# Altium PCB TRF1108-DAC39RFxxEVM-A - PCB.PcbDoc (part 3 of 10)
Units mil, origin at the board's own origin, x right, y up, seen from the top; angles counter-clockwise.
Board outline 4951.22 x 2726.56 mil, 16 copper layers (Top Layer, L2 GND1, L3 PWR1, L4 GND2, L5 PWR2, L6 GND3, L7 Ctrl Signal 1, L8 GND4, L9 GND5, L10 Ctrl Signal 2, L11 GND6, L12 PWR3, L13 GND7, L14 PWR4, L15 GND8, Bottom Layer), stack 80.2 mil thick; 705 components, 433 nets, 3633 pads, 1678 vias.
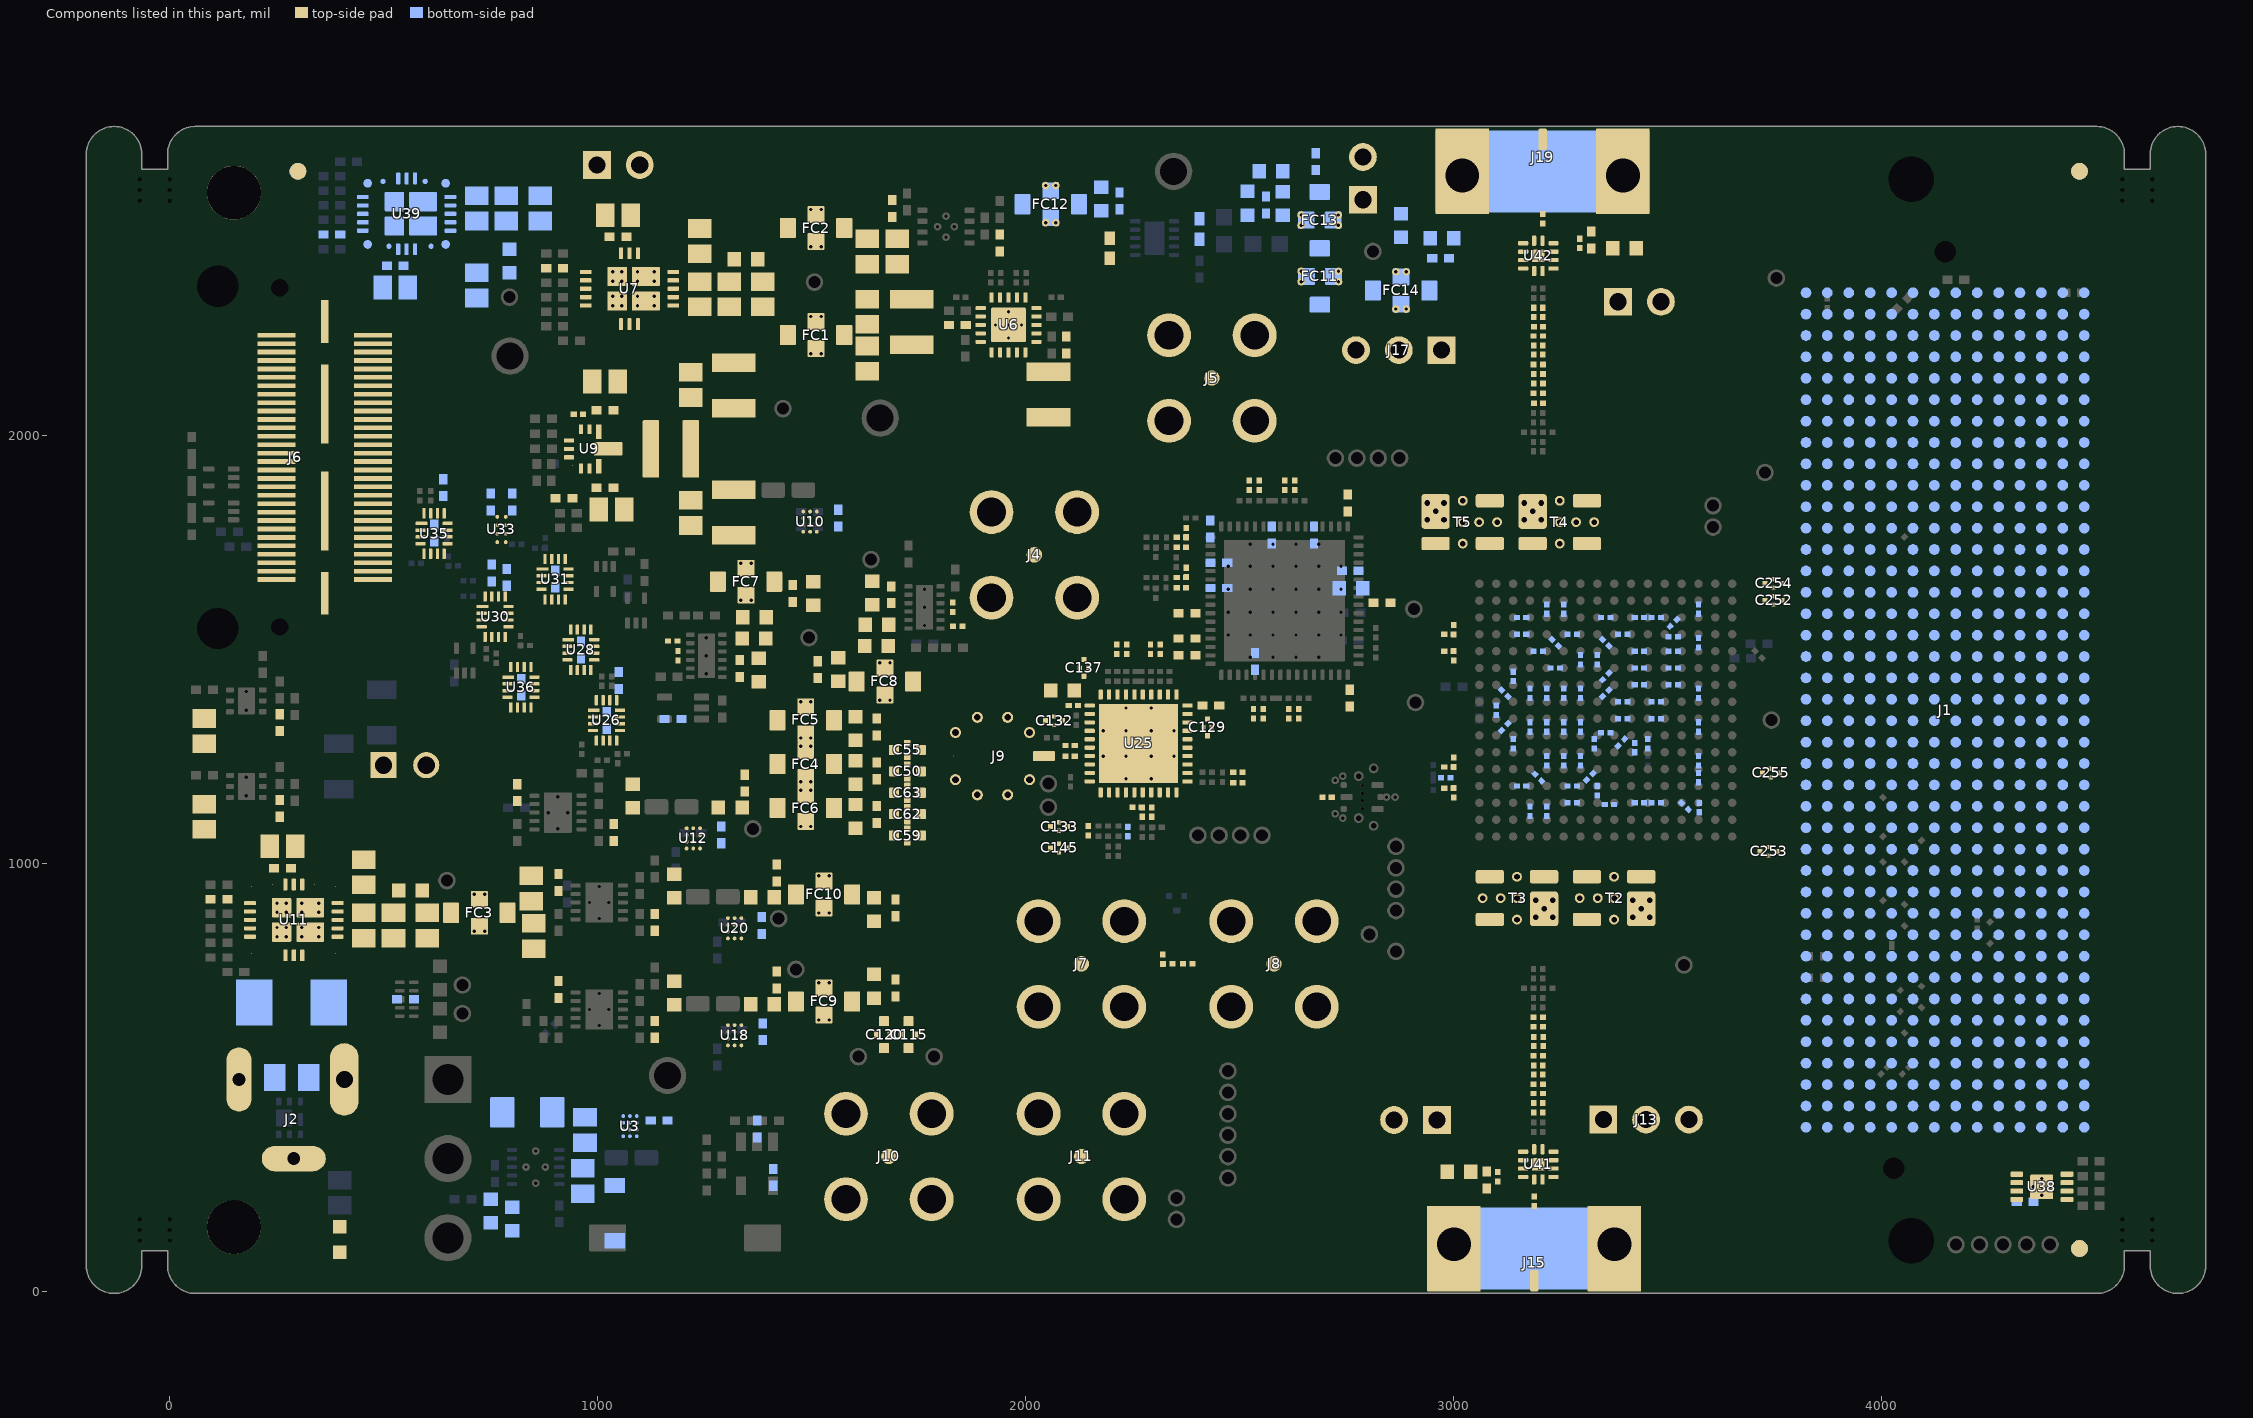
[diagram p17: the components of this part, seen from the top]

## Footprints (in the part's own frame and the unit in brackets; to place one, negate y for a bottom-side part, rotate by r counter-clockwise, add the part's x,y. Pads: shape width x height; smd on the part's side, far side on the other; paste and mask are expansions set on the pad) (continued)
RDU0028A [mm]
  round 0.025 smd mask+0.05: 1(-1.987,2.487) 2(-2.1,1.25) 6(-2.1,-1.25) 7(-1.987,-2.488) 13(1.987,-2.488) 14(2.1,-1.25) 18(2.1,1.25) 19(1.988,2.488)
  rrect40% 0.7x0.25 smd paste+0 mask+0.05: 3(-2.1,0.5) 4(-2.1,0) 5(-2.1,-0.5) 15(2.1,-0.5) 16(2.1,0) 17(2.1,0.5)
  rrect40% 0.25x0.7 smd paste+0 mask+0.05: 8(-1,-2.6) 9(-0.5,-2.6) 10(0,-2.6) 11(0.5,-2.6) 12(1,-2.6) 20(1,2.6) 21(0.5,2.6) 22(0,2.6) 23(-0.5,2.6) 24(-1,2.6)
  round 0.454 hole 0.2 mask+0.102: 25(-1,1) 25(-1,0.45) 25(-0.45,1) 25(-0.45,0.45) 26(-1,-0.475) 26(-1,-1.475) 26(-0.45,-0.475) 26(-0.45,-1.475) 27(0.45,-0.475) 27(0.45,-1.475) 27(1,-0.475) 27(1,-1.475) 28(0.45,1) 28(0.45,0.45) 28(1,1) 28(1,0.45)
  rrect9% 1.15x1.15 smd paste-1000 mask+0.05: 25(-0.725,0.725) 28(0.725,0.725)
  rrect9% 1.15x1.65 smd paste-1000 mask+0.05: 26(-0.725,-0.975) 27(0.725,-0.975)
  Top Layer region: -1.575,2.95 -1.55,2.943 -1.532,2.925 -1.525,2.9 -1.525,2.9 -1.525,2.075 -1.529,2.056 -1.54,2.04 -1.556,2.029 -1.575,2.025 -1.575,2.025 -2.4,2.025 -2.423,2.033 -2.439,2.051 -2.445,2.075 -2.445,2.075 -2.45,2.225 -2.443,2.25 -2.425,2.268 -2.4,2.275 -2.4,2.275 -2.225,2.275 -2.187,2.283 -2.154,2.304 -2.133,2.337 -2.125,2.375 -2.125,2.375 -2.125,2.575 -2.118,2.6 -2.1,2.618 -2.075,2.625 -2.075,2.625 -1.875,2.625 -1.837,2.633 -1.804,2.654 -1.783,2.687 -1.775,2.725 -1.775,2.725 -1.775,2.9 -1.768,2.925 -1.75,2.943 -1.725,2.95 -1.725,2.95
  Top Layer region: -1.575,-2.95 -1.55,-2.943 -1.532,-2.925 -1.525,-2.9 -1.525,-2.9 -1.525,-2.075 -1.529,-2.056 -1.54,-2.04 -1.556,-2.029 -1.575,-2.025 -1.575,-2.025 -2.4,-2.025 -2.423,-2.033 -2.439,-2.051 -2.445,-2.075 -2.445,-2.075 -2.45,-2.225 -2.443,-2.25 -2.425,-2.268 -2.4,-2.275 -2.4,-2.275 -2.225,-2.275 -2.187,-2.283 -2.154,-2.304 -2.133,-2.337 -2.125,-2.375 -2.125,-2.375 -2.125,-2.575 -2.118,-2.6 -2.1,-2.618 -2.075,-2.625 -2.075,-2.625 -1.875,-2.625 -1.837,-2.633 -1.804,-2.654 -1.783,-2.687 -1.775,-2.725 -1.775,-2.725 -1.775,-2.9 -1.768,-2.925 -1.75,-2.943 -1.725,-2.95 -1.725,-2.95
  Top Layer region: -2.4,-0.875 -1.8,-0.875 -1.775,-0.882 -1.757,-0.9 -1.75,-0.925 -1.75,-0.925 -1.75,-1.575 -1.754,-1.594 -1.765,-1.61 -1.781,-1.621 -1.8,-1.625 -1.8,-1.625 -2.4,-1.625 -2.419,-1.621 -2.435,-1.61 -2.446,-1.594 -2.45,-1.575 -2.45,-1.575 -2.45,-1.425 -2.443,-1.4 -2.425,-1.382 -2.4,-1.375 -2.4,-1.375 -2.225,-1.375 -2.187,-1.367 -2.154,-1.346 -2.133,-1.313 -2.125,-1.275 -2.125,-1.275 -2.125,-1.225 -2.138,-1.175 -2.175,-1.138 -2.225,-1.125 -2.225,-1.125 -2.4,-1.125 -2.419,-1.121 -2.435,-1.11 -2.446,-1.094 -2.45,-1.075 -2.45,-1.075 -2.45,-0.925 -2.443,-0.9 -2.425,-0.882 -2.4,-0.875
  Top Layer region: -2.4,1.625 -1.8,1.625 -1.781,1.621 -1.765,1.61 -1.754,1.594 -1.75,1.575 -1.75,1.575 -1.75,0.925 -1.754,0.906 -1.765,0.89 -1.781,0.879 -1.8,0.875 -1.8,0.875 -2.4,0.875 -2.419,0.879 -2.435,0.89 -2.446,0.906 -2.45,0.925 -2.45,0.925 -2.45,1.075 -2.443,1.1 -2.425,1.118 -2.4,1.125 -2.4,1.125 -2.225,1.125 -2.187,1.133 -2.154,1.154 -2.133,1.187 -2.125,1.225 -2.125,1.225 -2.125,1.275 -2.138,1.325 -2.175,1.362 -2.225,1.375 -2.225,1.375 -2.4,1.375 -2.419,1.379 -2.435,1.39 -2.446,1.406 -2.45,1.425 -2.45,1.425 -2.45,1.575 -2.443,1.6 -2.425,1.618 -2.4,1.625
  Top Layer region: 1.575,2.95 1.55,2.943 1.532,2.925 1.525,2.9 1.525,2.9 1.525,2.075 1.529,2.056 1.54,2.04 1.556,2.029 1.575,2.025 1.575,2.025 2.4,2.025 2.423,2.033 2.439,2.051 2.445,2.075 2.445,2.075 2.45,2.225 2.443,2.25 2.425,2.268 2.4,2.275 2.4,2.275 2.225,2.275 2.187,2.283 2.154,2.304 2.133,2.337 2.125,2.375 2.125,2.375 2.125,2.575 2.118,2.6 2.1,2.618 2.075,2.625 2.075,2.625 1.875,2.625 1.837,2.633 1.804,2.654 1.783,2.687 1.775,2.725 1.775,2.725 1.775,2.9 1.768,2.925 1.75,2.943 1.725,2.95 1.725,2.95
  Top Layer region: 2.4,0.875 1.8,0.875 1.775,0.882 1.757,0.9 1.75,0.925 1.75,0.925 1.75,1.575 1.754,1.594 1.765,1.61 1.781,1.621 1.8,1.625 1.8,1.625 2.4,1.625 2.419,1.621 2.435,1.61 2.446,1.594 2.45,1.575 2.45,1.575 2.45,1.425 2.443,1.4 2.425,1.382 2.4,1.375 2.4,1.375 2.225,1.375 2.187,1.367 2.154,1.346 2.133,1.313 2.125,1.275 2.125,1.275 2.125,1.225 2.138,1.175 2.175,1.138 2.225,1.125 2.225,1.125 2.4,1.125 2.419,1.121 2.435,1.11 2.446,1.094 2.45,1.075 2.45,1.075 2.45,0.925 2.443,0.9 2.425,0.882 2.4,0.875
  Top Layer region: 2.4,-1.625 1.8,-1.625 1.775,-1.618 1.757,-1.6 1.75,-1.575 1.75,-1.575 1.75,-0.925 1.754,-0.906 1.765,-0.89 1.781,-0.879 1.8,-0.875 1.8,-0.875 2.4,-0.875 2.419,-0.879 2.435,-0.89 2.446,-0.906 2.45,-0.925 2.45,-0.925 2.45,-1.075 2.443,-1.1 2.425,-1.118 2.4,-1.125 2.4,-1.125 2.225,-1.125 2.187,-1.133 2.154,-1.154 2.133,-1.187 2.125,-1.225 2.125,-1.225 2.125,-1.275 2.138,-1.325 2.175,-1.362 2.225,-1.375 2.225,-1.375 2.4,-1.375 2.419,-1.379 2.435,-1.39 2.446,-1.406 2.45,-1.425 2.45,-1.425 2.45,-1.575 2.443,-1.6 2.425,-1.618 2.4,-1.625
  Top Layer region: 1.575,-2.95 1.55,-2.943 1.532,-2.925 1.525,-2.9 1.525,-2.9 1.525,-2.075 1.529,-2.056 1.54,-2.04 1.556,-2.029 1.575,-2.025 1.575,-2.025 2.4,-2.025 2.423,-2.033 2.439,-2.051 2.445,-2.075 2.445,-2.075 2.45,-2.225 2.443,-2.25 2.425,-2.268 2.4,-2.275 2.4,-2.275 2.225,-2.275 2.187,-2.283 2.154,-2.304 2.133,-2.337 2.125,-2.375 2.125,-2.375 2.125,-2.575 2.118,-2.6 2.1,-2.618 2.075,-2.625 2.075,-2.625 1.875,-2.625 1.837,-2.633 1.804,-2.654 1.783,-2.687 1.775,-2.725 1.775,-2.725 1.775,-2.9 1.768,-2.925 1.75,-2.943 1.725,-2.95 1.725,-2.95
  silkscreen extent -3.2,-3.13 2.63,3.13, body extent -2.55,-3.05 2.55,3.05, height 0.25
RDU0028A-MFG [mm]
  round 0.52 smd paste+0 mask+0: 1(-1.814,2.314) 7(-1.814,-2.314) 13(1.814,-2.314) 19(1.814,2.314)
  round 0.315 smd paste+0 mask+0: 2(-1.925,1.4) 6(-1.925,-1.1) 14(1.925,-1.45) 18(1.925,1.05)
  rrect40% 0.7x0.25 smd paste+0 mask+0: 3(-2.1,0.5) 4(-2.1,0) 5(-2.1,-0.5) 15(2.1,-0.5) 16(2.1,0) 17(2.1,0.5)
  rrect40% 0.25x0.7 smd paste+0 mask+0: 8(-1,-2.6) 9(-0.5,-2.6) 10(0,-2.6) 11(0.5,-2.6) 12(1,-2.6) 20(1,2.6) 21(0.5,2.6) 22(0,2.6) 23(-0.5,2.6) 24(-1,2.6)
  rrect9% 1.15x1.15 smd paste-1000 mask+0: 25(-0.725,0.725) 28(0.725,0.725)
  rrect9% 1.15x1.65 smd paste-1000 mask+0: 26(-0.725,-0.975) 27(0.725,-0.975)
  Top Layer region: -1.575,2.95 -1.55,2.943 -1.532,2.925 -1.525,2.9 -1.525,2.9 -1.525,2.075 -1.529,2.056 -1.54,2.04 -1.556,2.029 -1.575,2.025 -1.575,2.025 -2.4,2.025 -2.423,2.033 -2.439,2.051 -2.445,2.075 -2.445,2.075 -2.45,2.225 -2.443,2.25 -2.425,2.268 -2.4,2.275 -2.4,2.275 -2.225,2.275 -2.187,2.283 -2.154,2.304 -2.133,2.337 -2.125,2.375 -2.125,2.375 -2.125,2.575 -2.118,2.6 -2.1,2.618 -2.075,2.625 -2.075,2.625 -1.875,2.625 -1.837,2.633 -1.804,2.654 -1.783,2.687 -1.775,2.725 -1.775,2.725 -1.775,2.9 -1.768,2.925 -1.75,2.943 -1.725,2.95 -1.725,2.95
  Top Layer region: -1.575,-2.95 -1.55,-2.943 -1.532,-2.925 -1.525,-2.9 -1.525,-2.9 -1.525,-2.075 -1.529,-2.056 -1.54,-2.04 -1.556,-2.029 -1.575,-2.025 -1.575,-2.025 -2.4,-2.025 -2.423,-2.033 -2.439,-2.051 -2.445,-2.075 -2.445,-2.075 -2.45,-2.225 -2.443,-2.25 -2.425,-2.268 -2.4,-2.275 -2.4,-2.275 -2.225,-2.275 -2.187,-2.283 -2.154,-2.304 -2.133,-2.337 -2.125,-2.375 -2.125,-2.375 -2.125,-2.575 -2.118,-2.6 -2.1,-2.618 -2.075,-2.625 -2.075,-2.625 -1.875,-2.625 -1.837,-2.633 -1.804,-2.654 -1.783,-2.687 -1.775,-2.725 -1.775,-2.725 -1.775,-2.9 -1.768,-2.925 -1.75,-2.943 -1.725,-2.95 -1.725,-2.95
  Top Layer region: 1.575,-2.95 1.55,-2.943 1.532,-2.925 1.525,-2.9 1.525,-2.9 1.525,-2.075 1.529,-2.056 1.54,-2.04 1.556,-2.029 1.575,-2.025 1.575,-2.025 2.4,-2.025 2.423,-2.033 2.439,-2.051 2.445,-2.075 2.445,-2.075 2.45,-2.225 2.443,-2.25 2.425,-2.268 2.4,-2.275 2.4,-2.275 2.225,-2.275 2.187,-2.283 2.154,-2.304 2.133,-2.337 2.125,-2.375 2.125,-2.375 2.125,-2.575 2.118,-2.6 2.1,-2.618 2.075,-2.625 2.075,-2.625 1.875,-2.625 1.837,-2.633 1.804,-2.654 1.783,-2.687 1.775,-2.725 1.775,-2.725 1.775,-2.9 1.768,-2.925 1.75,-2.943 1.725,-2.95 1.725,-2.95
  Top Layer region: 1.575,2.95 1.55,2.943 1.532,2.925 1.525,2.9 1.525,2.9 1.525,2.075 1.529,2.056 1.54,2.04 1.556,2.029 1.575,2.025 1.575,2.025 2.4,2.025 2.423,2.033 2.439,2.051 2.445,2.075 2.445,2.075 2.45,2.225 2.443,2.25 2.425,2.268 2.4,2.275 2.4,2.275 2.225,2.275 2.187,2.283 2.154,2.304 2.133,2.337 2.125,2.375 2.125,2.375 2.125,2.575 2.118,2.6 2.1,2.618 2.075,2.625 2.075,2.625 1.875,2.625 1.837,2.633 1.804,2.654 1.783,2.687 1.775,2.725 1.775,2.725 1.775,2.9 1.768,2.925 1.75,2.943 1.725,2.95 1.725,2.95
  Top Layer region: -2.4,1.625 -1.8,1.625 -1.781,1.621 -1.765,1.61 -1.754,1.594 -1.75,1.575 -1.75,1.575 -1.75,0.925 -1.754,0.906 -1.765,0.89 -1.781,0.879 -1.8,0.875 -1.8,0.875 -2.4,0.875 -2.419,0.879 -2.435,0.89 -2.446,0.906 -2.45,0.925 -2.45,0.925 -2.45,1.075 -2.443,1.1 -2.425,1.118 -2.4,1.125 -2.4,1.125 -2.225,1.125 -2.187,1.133 -2.154,1.154 -2.133,1.187 -2.125,1.225 -2.125,1.225 -2.125,1.275 -2.138,1.325 -2.175,1.362 -2.225,1.375 -2.225,1.375 -2.4,1.375 -2.419,1.379 -2.435,1.39 -2.446,1.406 -2.45,1.425 -2.45,1.425 -2.45,1.575 -2.443,1.6 -2.425,1.618 -2.4,1.625
  Top Layer region: -2.4,-0.875 -1.8,-0.875 -1.775,-0.882 -1.757,-0.9 -1.75,-0.925 -1.75,-0.925 -1.75,-1.575 -1.754,-1.594 -1.765,-1.61 -1.781,-1.621 -1.8,-1.625 -1.8,-1.625 -2.4,-1.625 -2.419,-1.621 -2.435,-1.61 -2.446,-1.594 -2.45,-1.575 -2.45,-1.575 -2.45,-1.425 -2.443,-1.4 -2.425,-1.382 -2.4,-1.375 -2.4,-1.375 -2.225,-1.375 -2.187,-1.367 -2.154,-1.346 -2.133,-1.313 -2.125,-1.275 -2.125,-1.275 -2.125,-1.225 -2.138,-1.175 -2.175,-1.138 -2.225,-1.125 -2.225,-1.125 -2.4,-1.125 -2.419,-1.121 -2.435,-1.11 -2.446,-1.094 -2.45,-1.075 -2.45,-1.075 -2.45,-0.925 -2.443,-0.9 -2.425,-0.882 -2.4,-0.875
  Top Layer region: 2.4,-1.625 1.8,-1.625 1.775,-1.618 1.757,-1.6 1.75,-1.575 1.75,-1.575 1.75,-0.925 1.754,-0.906 1.765,-0.89 1.781,-0.879 1.8,-0.875 1.8,-0.875 2.4,-0.875 2.419,-0.879 2.435,-0.89 2.446,-0.906 2.45,-0.925 2.45,-0.925 2.45,-1.075 2.443,-1.1 2.425,-1.118 2.4,-1.125 2.4,-1.125 2.225,-1.125 2.187,-1.133 2.154,-1.154 2.133,-1.187 2.125,-1.225 2.125,-1.225 2.125,-1.275 2.138,-1.325 2.175,-1.362 2.225,-1.375 2.225,-1.375 2.4,-1.375 2.419,-1.379 2.435,-1.39 2.446,-1.406 2.45,-1.425 2.45,-1.425 2.45,-1.575 2.443,-1.6 2.425,-1.618 2.4,-1.625
  Top Layer region: 2.4,0.875 1.8,0.875 1.775,0.882 1.757,0.9 1.75,0.925 1.75,0.925 1.75,1.575 1.754,1.594 1.765,1.61 1.781,1.621 1.8,1.625 1.8,1.625 2.4,1.625 2.419,1.621 2.435,1.61 2.446,1.594 2.45,1.575 2.45,1.575 2.45,1.425 2.443,1.4 2.425,1.382 2.4,1.375 2.4,1.375 2.225,1.375 2.187,1.367 2.154,1.346 2.133,1.313 2.125,1.275 2.125,1.275 2.125,1.225 2.138,1.175 2.175,1.138 2.225,1.125 2.225,1.125 2.4,1.125 2.419,1.121 2.435,1.11 2.446,1.094 2.45,1.075 2.45,1.075 2.45,0.925 2.443,0.9 2.425,0.882 2.4,0.875
  silkscreen extent -3.2,-3.13 2.63,3.13, body extent -2.25,-2.75 2.25,2.75, height 1.9
RGR0020A [mm]
  rrect30% 0.6x0.24 smd paste+0 mask+0.07: 1(-1.65,1) 2(-1.65,0.5) 3(-1.65,0) 4(-1.65,-0.5) 5(-1.65,-1) 11(1.65,-1) 12(1.65,-0.5) 13(1.65,0) 14(1.65,0.5) 15(1.65,1)
  rrect30% 0.24x0.6 smd paste+0 mask+0.07: 6(-1,-1.625) 7(-0.5,-1.625) 8(0,-1.625) 9(0.5,-1.625) 10(1,-1.625) 16(1,1.625) 17(0.5,1.625) 18(0,1.625) 19(-0.5,1.625) 20(-1,1.625)
  round 0.454 hole 0.2 mask+0: 21(-0.775,0) 21(0,0.775) 21(0,0) 21(0,-0.775) 21(0.775,0)
  rrect5% 2.05x2.05 smd paste-1000 mask+0.07: 21(0,0)
  silkscreen extent -1.97,-1.83 1.83,1.92, body extent -2.25,-2.25 2.25,2.25, height 0.25
RHA0040C [mm]
  rrect40% 0.6x0.25 smd paste+0 mask+0.07: 1(-2.9,2.25) 2(-2.9,1.75) 3(-2.9,1.25) 4(-2.9,0.75) 5(-2.9,0.25) 6(-2.9,-0.25) 7(-2.9,-0.75) 8(-2.9,-1.25) 9(-2.9,-1.75) 10(-2.9,-2.25) 21(2.9,-2.25) 22(2.9,-1.75) 23(2.9,-1.25) 24(2.9,-0.75) 25(2.9,-0.25) 26(2.9,0.25) 27(2.9,0.75) 28(2.9,1.25) 29(2.9,1.75) 30(2.9,2.25)
  rrect40% 0.25x0.6 smd paste+0 mask+0.07: 11(-2.25,-2.9) 12(-1.75,-2.9) 13(-1.25,-2.9) 14(-0.75,-2.9) 15(-0.25,-2.9) 16(0.25,-2.9) 17(0.75,-2.9) 18(1.25,-2.9) 19(1.75,-2.9) 20(2.25,-2.9) 31(2.25,2.9) 32(1.75,2.9) 33(1.25,2.9) 34(0.75,2.9) 35(0.25,2.9) 36(-0.25,2.9) 37(-0.75,2.9) 38(-1.25,2.9) 39(-1.75,2.9) 40(-2.25,2.9)
  round 0.454 hole 0.2 mask+0: 41(-2.1,-0.75) 41(-2.1,0.75) 41(-0.75,0.75) 41(-0.75,2.1) 41(-0.75,-2.1) 41(-0.75,-0.75) 41(0.75,0.75) 41(0.75,2.1) 41(0.75,-2.1) 41(0.75,-0.75) 41(2.1,-0.75) 41(2.1,0.75)
  rrect2% 4.7x4.7 smd paste-1000 mask+0.07: 41(0,0)
  silkscreen extent -3.43,-3.05 3.05,3.52, body extent -3.3,-3.3 3.3,3.3, height 0.25
RPV0012A-MFG [mm]
  rrect40% 0.6x0.25 smd paste+0 mask+0: 1(-0.9,0.75) 2(-0.9,0.25) 3(-0.9,-0.25) 4(-0.9,-0.75) 7(0.9,-0.75) 8(0.9,-0.25) 9(0.9,0.25) 10(0.9,0.75)
  rrect40% 0.25x0.6 smd paste+0 mask+0: 5(-0.25,-0.9) 6(0.25,-0.9) 11(0.25,0.9) 12(-0.25,0.9)
  rrect13% 0.75x0.75 smd paste-1000 mask+0: 13(0,0)
  silkscreen extent -1.9,0.63 -1.65,0.87, body extent -1,-1 1,1, height 0.7
RPY0014A [mm]
  round 0.025 smd mask+0.05: 1(-1.213,0.987) 5(-1.212,-0.988) 9(0.975,-0.8) 11(0.975,0.8)
  rrect20% 0.575x0.25 smd paste+0 mask+0.05: 2(-1.412,0.5) 3(-1.412,0) 4(-1.412,-0.5)
  rrect20% 0.25x0.575 smd paste+0 mask+0.05: 6(-0.7,-1.162) 7(-0.2,-1.162) 13(-0.2,1.162) 14(-0.7,1.162)
  rrect10% 0.35x0.851 smd paste+0 mask+0.05: 8(0.35,-1.025) 12(0.35,1.025)
  rrect10% 1.675x0.8 smd paste-0.825 mask-0.826: 10(0.913,0)
  Top Layer region: 1.237,0.6 1.65,0.6 1.669,0.604 1.685,0.615 1.696,0.631 1.7,0.65 1.7,0.65 1.7,0.95 1.696,0.969 1.685,0.985 1.669,0.996 1.65,1 1.65,1 1.175,1 1.175,1.4 1.175,1.4 1.175,1.4 1.171,1.419 1.16,1.435 1.144,1.446 1.125,1.45 1.125,1.45 0.82,1.45 0.803,1.447 0.788,1.437 0.778,1.422 0.775,1.405 0.775,1.405 0.775,0.64 0.778,0.625 0.787,0.612 0.8,0.603 0.815,0.6 0.815,0.6 0.874,0.6
  Top Layer region: 1.237,-0.6 1.65,-0.6 1.669,-0.604 1.685,-0.615 1.696,-0.631 1.7,-0.65 1.7,-0.65 1.7,-0.95 1.696,-0.969 1.685,-0.985 1.669,-0.996 1.65,-1 1.65,-1 1.175,-1 1.175,-1.4 1.175,-1.4 1.175,-1.4 1.171,-1.419 1.16,-1.435 1.144,-1.446 1.125,-1.45 1.125,-1.45 0.82,-1.45 0.803,-1.447 0.788,-1.437 0.778,-1.422 0.775,-1.405 0.775,-1.405 0.775,-0.64 0.778,-0.625 0.787,-0.612 0.8,-0.603 0.815,-0.6 0.815,-0.6 0.874,-0.6
  Top Layer region: -1.115,-0.875 -1.1,-0.878 -1.087,-0.887 -1.078,-0.9 -1.075,-0.915 -1.075,-0.915 -1.075,-1.4 -1.075,-1.4 -1.075,-1.405 -1.078,-1.422 -1.088,-1.437 -1.103,-1.447 -1.12,-1.45 -1.12,-1.45 -1.3,-1.45 -1.319,-1.446 -1.335,-1.435 -1.346,-1.419 -1.35,-1.4 -1.35,-1.4 -1.35,-1.1 -1.655,-1.1 -1.672,-1.097 -1.687,-1.087 -1.696,-1.072 -1.7,-1.055 -1.7,-1.055 -1.7,-0.915 -1.697,-0.9 -1.688,-0.887 -1.675,-0.878 -1.66,-0.875 -1.66,-0.875
  Top Layer region: -1.115,0.875 -1.1,0.878 -1.087,0.887 -1.078,0.9 -1.075,0.915 -1.075,0.915 -1.075,1.4 -1.075,1.4 -1.075,1.405 -1.078,1.422 -1.088,1.437 -1.103,1.447 -1.12,1.45 -1.12,1.45 -1.3,1.45 -1.319,1.446 -1.335,1.435 -1.346,1.419 -1.35,1.4 -1.35,1.4 -1.35,1.1 -1.655,1.1 -1.672,1.097 -1.687,1.087 -1.697,1.072 -1.7,1.055 -1.7,1.055 -1.7,0.915 -1.697,0.9 -1.688,0.887 -1.675,0.878 -1.66,0.875 -1.66,0.875
  silkscreen extent -1.92,-1.63 1.92,2.12, body extent -1.5,-1.25 1.5,1.25, height 1.01
RSV0016A [mm] "QFN, 16-Leads, Body 1.8x2.6mm, Pitch 0.4mm, TI Recommended"
  rrect25% 0.7x0.2 smd mask+0.05: 1(-0.75,0.6)
  rrect25% 0.6x0.2 smd mask+0.05: 2(-0.8,0.2) 3(-0.8,-0.2) 4(-0.8,-0.6) 9(0.8,-0.6) 10(0.8,-0.2) 11(0.8,0.2) 12(0.8,0.6)
  rrect25% 0.2x0.6 smd mask+0.05: 5(-0.6,-1.2) 6(-0.2,-1.2) 7(0.2,-1.2) 8(0.6,-1.2) 13(0.6,1.2) 14(0.2,1.2) 15(-0.2,1.2) 16(-0.6,1.2)
  silkscreen extent -1.08,-1.33 1.08,1.45, body extent -0.92,-1.32 0.92,1.33, height 0.56
SAMTEC_ASP-184330-01 [mil] "Terminal Array, 1.27mm, 40x14, SMT"
  round 25 smd far side paste-25.2: A1(975,-225) A2(925,-225) A3(875,-225) A4(825,-225) A5(775,-225) A6(725,-225) A7(675,-225) A8(625,-225) A9(575,-225) A10(525,-225) A11(475,-225) A12(425,-225) A13(375,-225) A14(325,-225) A15(275,-225) A16(225,-225) A17(175,-225) A18(125,-225) A19(75,-225) A20(25,-225) A21(-25,-225) A22(-75,-225) A23(-125,-225) A24(-175,-225) A25(-225,-225) A26(-275,-225) A27(-325,-225) A28(-375,-225) A29(-425,-225) A30(-475,-225) A31(-525,-225) A32(-575,-225) A33(-625,-225) A34(-675,-225) A35(-725,-225) A36(-775,-225) A37(-825,-225) A38(-875,-225) A39(-925,-225) A40(-975,-225) B1(975,-175) B2(925,-175) B3(875,-175) B4(825,-175) B5(775,-175) B6(725,-175) B7(675,-175) B8(625,-175) B9(575,-175) B10(525,-175) B11(475,-175) B12(425,-175) B13(375,-175) B14(325,-175) B15(275,-175) B16(225,-175) B17(175,-175) B18(125,-175) B19(75,-175) B20(25,-175) B21(-25,-175) B22(-75,-175) B23(-125,-175) B24(-175,-175) B25(-225,-175) B26(-275,-175) B27(-325,-175) B28(-375,-175) B29(-425,-175) B30(-475,-175) B31(-525,-175) B32(-575,-175) B33(-625,-175) B34(-675,-175) B35(-725,-175) B36(-775,-175) B37(-825,-175) B38(-875,-175) B39(-925,-175) B40(-975,-175) C1(975,-125) C2(925,-125) C3(875,-125) C4(825,-125) C5(775,-125) C6(725,-125) C7(675,-125) C8(625,-125) C9(575,-125) C10(525,-125) C11(475,-125) C12(425,-125) C13(375,-125) C14(325,-125) C15(275,-125) C16(225,-125) C17(175,-125) C18(125,-125) C19(75,-125) C20(25,-125) C21(-25,-125) C22(-75,-125) C23(-125,-125) C24(-175,-125) C25(-225,-125) C26(-275,-125) C27(-325,-125) C28(-375,-125) C29(-425,-125) C30(-475,-125) C31(-525,-125) C32(-575,-125) C33(-625,-125) C34(-675,-125) C35(-725,-125) C36(-775,-125) C37(-825,-125) C38(-875,-125) C39(-925,-125) C40(-975,-125) D1(975,-75) D2(925,-75) D3(875,-75) D4(825,-75) D5(775,-75) D6(725,-75) D7(675,-75) D8(625,-75) D9(575,-75) D10(525,-75) D11(475,-75) D12(425,-75) D13(375,-75) D14(325,-75) D15(275,-75) D16(225,-75) D17(175,-75) D18(125,-75) D19(75,-75) D20(25,-75) D21(-25,-75) D22(-75,-75) D23(-125,-75) D24(-175,-75) D25(-225,-75) D26(-275,-75) D27(-325,-75) D28(-375,-75) D29(-425,-75) D30(-475,-75) D31(-525,-75) D32(-575,-75) D33(-625,-75) D34(-675,-75) D35(-725,-75) D36(-775,-75) D37(-825,-75) D38(-875,-75) D39(-925,-75) D40(-975,-75) E1(975,-25) E2(925,-25) E3(875,-25) E4(825,-25) E5(775,-25) E6(725,-25) E7(675,-25) E8(625,-25) E9(575,-25) E10(525,-25) E11(475,-25) E12(425,-25) E13(375,-25) E14(325,-25) E15(275,-25) E16(225,-25) E17(175,-25) E18(125,-25) E19(75,-25) E20(25,-25) E21(-25,-25) E22(-75,-25) E23(-125,-25) E24(-175,-25) E25(-225,-25) E26(-275,-25) E27(-325,-25) E28(-375,-25) E29(-425,-25) E30(-475,-25) E31(-525,-25) E32(-575,-25) E33(-625,-25) E34(-675,-25) E35(-725,-25) E36(-775,-25) E37(-825,-25) E38(-875,-25) E39(-925,-25) E40(-975,-25) F1(975,25) F2(925,25) F3(875,25) F4(825,25) F5(775,25) F6(725,25) F7(675,25) F8(625,25) F9(575,25) F10(525,25) F11(475,25) F12(425,25) F13(375,25) F14(325,25) F15(275,25) F16(225,25) F17(175,25) F18(125,25) F19(75,25) F20(25,25) F21(-25,25) F22(-75,25) F23(-125,25) F24(-175,25) F25(-225,25) F26(-275,25) F27(-325,25) F28(-375,25) F29(-425,25) F30(-475,25) F31(-525,25) F32(-575,25) F33(-625,25) F34(-675,25) F35(-725,25) F36(-775,25) F37(-825,25) F38(-875,25) F39(-925,25) F40(-975,25) G1(975,75) G2(925,75) G3(875,75) G4(825,75) G5(775,75) G6(725,75) G7(675,75) G8(625,75) G9(575,75) G10(525,75) G11(475,75) G12(425,75) G13(375,75) G14(325,75) G15(275,75) G16(225,75) G17(175,75) G18(125,75) G19(75,75) G20(25,75) G21(-25,75) G22(-75,75) G23(-125,75) G24(-175,75) G25(-225,75) G26(-275,75) G27(-325,75) G28(-375,75) G29(-425,75) G30(-475,75) G31(-525,75) G32(-575,75) G33(-625,75) G34(-675,75) G35(-725,75) G36(-775,75) G37(-825,75) G38(-875,75) G39(-925,75) G40(-975,75) H1(975,125) H2(925,125) H3(875,125) H4(825,125) H5(775,125) H6(725,125) H7(675,125) H8(625,125) H9(575,125) H10(525,125) H11(475,125) H12(425,125) H13(375,125) H14(325,125) H15(275,125) H16(225,125) H17(175,125) H18(125,125) H19(75,125) H20(25,125) H21(-25,125) H22(-75,125) H23(-125,125) H24(-175,125) H25(-225,125) H26(-275,125) H27(-325,125) H28(-375,125) H29(-425,125) H30(-475,125) H31(-525,125) H32(-575,125) H33(-625,125) H34(-675,125) H35(-725,125) H36(-775,125) H37(-825,125) H38(-875,125) H39(-925,125) H40(-975,125) J1(975,175) J2(925,175) J3(875,175) J4(825,175) J5(775,175) J6(725,175) J7(675,175) J8(625,175) J9(575,175) J10(525,175) J11(475,175) J12(425,175) J13(375,175) J14(325,175) J15(275,175) J16(225,175) J17(175,175) J18(125,175) J19(75,175) J20(25,175) J21(-25,175) J22(-75,175) J23(-125,175) J24(-175,175) J25(-225,175) J26(-275,175) J27(-325,175) J28(-375,175) J29(-425,175) J30(-475,175) J31(-525,175) J32(-575,175) J33(-625,175) J34(-675,175) J35(-725,175) J36(-775,175) J37(-825,175) J38(-875,175) J39(-925,175) J40(-975,175) K1(975,225) K2(925,225) K3(875,225) K4(825,225) K5(775,225) K6(725,225) K7(675,225) K8(625,225) K9(575,225) K10(525,225) K11(475,225) K12(425,225) K13(375,225) K14(325,225) K15(275,225) K16(225,225) K17(175,225) K18(125,225) K19(75,225) K20(25,225) K21(-25,225) K22(-75,225) K23(-125,225) K24(-175,225) K25(-225,225) K26(-275,225) K27(-325,225) K28(-375,225) K29(-425,225) K30(-475,225) K31(-525,225) K32(-575,225) K33(-625,225) K34(-675,225) K35(-725,225) K36(-775,225) K37(-825,225) K38(-875,225) K39(-925,225) K40(-975,225) L1(975,275) L2(925,275) L3(875,275) L4(825,275) L5(775,275) L6(725,275) L7(675,275) L8(625,275) L9(575,275) L10(525,275) L11(475,275) L12(425,275) L13(375,275) L14(325,275) L15(275,275) L16(225,275) L17(175,275) L18(125,275) L19(75,275) L20(25,275) L21(-25,275) L22(-75,275) L23(-125,275) L24(-175,275) L25(-225,275) L26(-275,275) L27(-325,275) L28(-375,275) L29(-425,275) L30(-475,275) L31(-525,275) L32(-575,275) L33(-625,275) L34(-675,275) L35(-725,275) L36(-775,275) L37(-825,275) L38(-875,275) L39(-925,275) L40(-975,275) M1(975,325) M2(925,325) M3(875,325) M4(825,325) M5(775,325) M6(725,325) M7(675,325) M8(625,325) M9(575,325) M10(525,325) M11(475,325) M12(425,325) M13(375,325) M14(325,325) M15(275,325) M16(225,325) M17(175,325) M18(125,325) M19(75,325) M20(25,325) M21(-25,325) M22(-75,325) M23(-125,325) M24(-175,325) M25(-225,325) M26(-275,325) M27(-325,325) M28(-375,325) M29(-425,325) M30(-475,325) M31(-525,325) M32(-575,325) M33(-625,325) M34(-675,325) M35(-725,325) M36(-775,325) M37(-825,325) M38(-875,325) M39(-925,325) M40(-975,325) Y1(975,-325) Y2(925,-325) Y3(875,-325) Y4(825,-325) Y5(775,-325) Y6(725,-325) Y7(675,-325) Y8(625,-325) Y9(575,-325) Y10(525,-325) Y11(475,-325) Y12(425,-325) Y13(375,-325) Y14(325,-325) Y15(275,-325) Y16(225,-325) Y17(175,-325) Y18(125,-325) Y19(75,-325) Y20(25,-325) Y21(-25,-325) Y22(-75,-325) Y23(-125,-325) Y24(-175,-325) Y25(-225,-325) Y26(-275,-325) Y27(-325,-325) Y28(-375,-325) Y29(-425,-325) Y30(-475,-325) Y31(-525,-325) Y32(-575,-325) Y33(-625,-325) Y34(-675,-325) Y35(-725,-325) Y36(-775,-325) Y37(-825,-325) Y38(-875,-325) Y39(-925,-325) Y40(-975,-325) Z1(975,-275) Z2(925,-275) Z3(875,-275) Z4(825,-275) Z5(775,-275) Z6(725,-275) Z7(675,-275) Z8(625,-275) Z9(575,-275) Z10(525,-275) Z11(475,-275) Z12(425,-275) Z13(375,-275) Z14(325,-275) Z15(275,-275) Z16(225,-275) Z17(175,-275) Z18(125,-275) Z19(75,-275) Z20(25,-275) Z21(-25,-275) Z22(-75,-275) Z23(-125,-275) Z24(-175,-275) Z25(-225,-275) Z26(-275,-275) Z27(-325,-275) Z28(-375,-275) Z29(-425,-275) Z30(-475,-275) Z31(-525,-275) Z32(-575,-275) Z33(-625,-275) Z34(-675,-275) Z35(-725,-275) Z36(-775,-275) Z37(-825,-275) Z38(-875,-275) Z39(-925,-275) Z40(-975,-275)
  round 0 hole 105.91 unplated: ""(-1240,79) ""(1240,79)
  round 0 hole 50 unplated: ""(-1070.5,120) ""(1070.5,0)
  round 25 on Bottom Paste: ""(-975,-325) ""(-975,-275) ""(-975,-225) ""(-975,-175) ""(-975,-125) ""(-975,-75) ""(-975,-25) ""(-975,25) ""(-975,75) ""(-975,125) ""(-975,175) ""(-975,225) ""(-975,275) ""(-975,325) ""(-925,-325) ""(-925,-275) ""(-925,-225) ""(-925,-175) ""(-925,-125) ""(-925,-75) ""(-925,-25) ""(-925,25) ""(-925,75) ""(-925,125) ""(-925,175) ""(-925,225) ""(-925,275) ""(-925,325) ""(-875,-325) ""(-875,-275) ""(-875,-225) ""(-875,-175) ""(-875,-125) ""(-875,-75) ""(-875,-25) ""(-875,25) ""(-875,75) ""(-875,125) ""(-875,175) ""(-875,225) ""(-875,275) ""(-875,325) ""(-825,-325) ""(-825,-275) ""(-825,-225) ""(-825,-175) ""(-825,-125) ""(-825,-75) ""(-825,-25) ""(-825,25) ""(-825,75) ""(-825,125) ""(-825,175) ""(-825,225) ""(-825,275) ""(-825,325) ""(-775,-325) ""(-775,-275) ""(-775,-225) ""(-775,-175) ""(-775,-125) ""(-775,-75) ""(-775,-25) ""(-775,25) ""(-775,75) ""(-775,125) ""(-775,175) ""(-775,225) ""(-775,275) ""(-775,325) ""(-725,-325) ""(-725,-275) ""(-725,-225) ""(-725,-175) ""(-725,-125) ""(-725,-75) ""(-725,-25) ""(-725,25) ""(-725,75) ""(-725,125) ""(-725,175) ""(-725,225) ""(-725,275) ""(-725,325) ""(-675,-325) ""(-675,-275) ""(-675,-225) ""(-675,-175) ""(-675,-125) ""(-675,-75) ""(-675,-25) ""(-675,25) ""(-675,75) ""(-675,125) ""(-675,175) ""(-675,225) ""(-675,275) ""(-675,325) ""(-625,-325) ""(-625,-275) ""(-625,-225) ""(-625,-175) ""(-625,-125) ""(-625,-75) ""(-625,-25) ""(-625,25) ""(-625,75) ""(-625,125) ""(-625,175) ""(-625,225) ""(-625,275) ""(-625,325) ""(-575,-325) ""(-575,-275) ""(-575,-225) ""(-575,-175) ""(-575,-125) ""(-575,-75) ""(-575,-25) ""(-575,25) ""(-575,75) ""(-575,125) ""(-575,175) ""(-575,225) ""(-575,275) ""(-575,325) ""(-525,-325) ""(-525,-275) ""(-525,-225) ""(-525,-175) ""(-525,-125) ""(-525,-75) ""(-525,-25) ""(-525,25) ""(-525,75) ""(-525,125) ""(-525,175) ""(-525,225) ""(-525,275) ""(-525,325) ""(-475,-325) ""(-475,-275) ""(-475,-225) ""(-475,-175) ""(-475,-125) ""(-475,-75) ""(-475,-25) ""(-475,25) ""(-475,75) ""(-475,125) ""(-475,175) ""(-475,225) ""(-475,275) ""(-475,325) ""(-425,-325) ""(-425,-275) ""(-425,-225) ""(-425,-175) ""(-425,-125) ""(-425,-75) ""(-425,-25) ""(-425,25) ""(-425,75) ""(-425,125) ""(-425,175) ""(-425,225) ""(-425,275) ""(-425,325) ""(-375,-325) ""(-375,-275) ""(-375,-225) ""(-375,-175) ""(-375,-125) ""(-375,-75) ""(-375,-25) ""(-375,25) ""(-375,75) ""(-375,125) ""(-375,175) ""(-375,225) ""(-375,275) ""(-375,325) ""(-325,-325) ""(-325,-275) ""(-325,-225) ""(-325,-175) ""(-325,-125) ""(-325,-75) ""(-325,-25) ""(-325,25) ""(-325,75) ""(-325,125) ""(-325,175) ""(-325,225) ""(-325,275) ""(-325,325) ""(-275,-325) ""(-275,-275) ""(-275,-225) ""(-275,-175) ""(-275,-125) ""(-275,-75) ""(-275,-25) ""(-275,25) ""(-275,75) ""(-275,125) ""(-275,175) ""(-275,225) ""(-275,275) ""(-275,325) ""(-225,275) ""(-225,325) ""(-225,-225) ""(-225,-175) ""(-225,-125) ""(-225,-75) ""(-225,-25) ""(-225,25) ""(-225,75) ""(-225,125) ""(-225,175) ""(-225,225) ""(-225,-325) ""(-225,-275) ""(-175,275) ""(-175,325) ""(-175,-225) ""(-175,-175) ""(-175,-125) ""(-175,-75) ""(-175,-25) ""(-175,25) ""(-175,75) ""(-175,125) ""(-175,175) ""(-175,225) ""(-175,-325) ""(-175,-275) ""(-125,125) ""(-125,175) ""(-125,225) ""(-125,275) ""(-125,325) ""(-125,-75) ""(-125,-25) ""(-125,25) ""(-125,75) ""(-125,-325) ""(-125,-275) ""(-125,-225) ""(-125,-175) ""(-125,-125) ""(-75,125) ""(-75,175) ""(-75,225) ""(-75,275) ""(-75,325) ""(-75,-75) ""(-75,-25) ""(-75,25) ""(-75,75) ""(-75,-325) ""(-75,-275) ""(-75,-225) ""(-75,-175) ""(-75,-125) ""(-25,325) ""(-25,275) ""(-25,225) ""(-25,175) ""(-25,125) ""(-25,75) ""(-25,-25) ""(-25,25) ""(-25,-75) ""(-25,-125) ""(-25,-175) ""(-25,-225) ""(-25,-275) ""(-25,-325) ""(25,325) ""(25,275) ""(25,225) ""(25,175) ""(25,125) ""(25,75) ""(25,-25) ""(25,25) ""(25,-75) ""(25,-125) ""(25,-175) ""(25,-225) ""(25,-275) ""(25,-325) ""(75,125) ""(75,175) ""(75,225) ""(75,275) ""(75,325) ""(75,-75) ""(75,-25) ""(75,25) ""(75,75) ""(75,-325) ""(75,-275) ""(75,-225) ""(75,-175) ""(75,-125) ""(125,125) ""(125,175) ""(125,225) ""(125,275) ""(125,325) ""(125,-75) ""(125,-25) ""(125,25) ""(125,75) ""(125,-325) ""(125,-275) ""(125,-225) ""(125,-175) ""(125,-125) ""(175,275) ""(175,325) ""(175,-225) ""(175,-175) ""(175,-125) ""(175,-75) ""(175,-25) ""(175,25) ""(175,75) ""(175,125) ""(175,175) ""(175,225) ""(175,-325) ""(175,-275) ""(225,275) ""(225,325) ""(225,-225) ""(225,-175) ""(225,-125) ""(225,-75) ""(225,-25) ""(225,25) ""(225,75) ""(225,125) ""(225,175) ""(225,225) ""(225,-325) ""(225,-275) ""(275,-325) ""(275,-275) ""(275,-225) ""(275,-175) ""(275,-125) ""(275,-75) ""(275,-25) ""(275,25) ""(275,75) ""(275,125) ""(275,175) ""(275,225) ""(275,275) ""(275,325) ""(325,-325) ""(325,-275) ""(325,-225) ""(325,-175) ""(325,-125) ""(325,-75) ""(325,-25) ""(325,25) ""(325,75) ""(325,125) ""(325,175) ""(325,225) ""(325,275) ""(325,325) ""(375,-325) ""(375,-275) ""(375,-225) ""(375,-175) ""(375,-125) ""(375,-75) ""(375,-25) ""(375,25) ""(375,75) ""(375,125) ""(375,175) ""(375,225) ""(375,275) ""(375,325) ""(425,-325) ""(425,-275) ""(425,-225) ""(425,-175) ""(425,-125) ""(425,-75) ""(425,-25) ""(425,25) ""(425,75) ""(425,125) ""(425,175) ""(425,225) ""(425,275) ""(425,325) ""(475,-325) ""(475,-275) ""(475,-225) ""(475,-175) ""(475,-125) ""(475,-75) ""(475,-25) ""(475,25) ""(475,75) ""(475,125) ""(475,175) ""(475,225) ""(475,275) ""(475,325) ""(525,-325) ""(525,-275) ""(525,-225) ""(525,-175) ""(525,-125) ""(525,-75) ""(525,-25) ""(525,25) ""(525,75) ""(525,125) ""(525,175) ""(525,225) ""(525,275) ""(525,325) ""(575,-325) ""(575,-275) ""(575,-225) ""(575,-175) ""(575,-125) ""(575,-75) ""(575,-25) ""(575,25) ""(575,75) ""(575,125) ""(575,175) ""(575,225) ""(575,275) ""(575,325) ""(625,-325) ""(625,-275) ""(625,-225) ""(625,-175) ""(625,-125) ""(625,-75) ""(625,-25) ""(625,25) ""(625,75) ""(625,125) ""(625,175) ""(625,225) ""(625,275) ""(625,325) ""(675,-325) ""(675,-275) ""(675,-225) ""(675,-175) ""(675,-125) ""(675,-75) ""(675,-25) ""(675,25) ""(675,75) ""(675,125) ""(675,175) ""(675,225) ""(675,275) ""(675,325) ""(725,-325) ""(725,-275) ""(725,-225) ""(725,-175) ""(725,-125) ""(725,-75) ""(725,-25) ""(725,25) ""(725,75) ""(725,125) ""(725,175) ""(725,225) ""(725,275) ""(725,325) ""(775,-325) ""(775,-275) ""(775,-225) ""(775,-175) ""(775,-125) ""(775,-75) ""(775,-25) ""(775,25) ""(775,75) ""(775,125) ""(775,175) ""(775,225) ""(775,275) ""(775,325) ""(825,-325) ""(825,-275) ""(825,-225) ""(825,-175) ""(825,-125) ""(825,-75) ""(825,-25) ""(825,25) ""(825,75) ""(825,125) ""(825,175) ""(825,225) ""(825,275) ""(825,325) ""(875,-325) ""(875,-275) ""(875,-225) ""(875,-175) ""(875,-125) ""(875,-75) ""(875,-25) ""(875,25) ""(875,75) ""(875,125) ""(875,175) ""(875,225) ""(875,275) ""(875,325) ""(925,-325) ""(925,-275) ""(925,-225) ""(925,-175) ""(925,-125) ""(925,-75) ""(925,-25) ""(925,25) ""(925,75) ""(925,125) ""(925,175) ""(925,225) ""(925,275) ""(925,325) ""(975,-325) ""(975,-275) ""(975,-225) ""(975,-175) ""(975,-125) ""(975,-75) ""(975,-25) ""(975,25) ""(975,75) ""(975,125) ""(975,175) ""(975,225) ""(975,275) ""(975,325)
  body extent -1098,-389 1133,389, height 289
SF-1206F500M-2_1206 [mm]
  rrect7% 1.45x1.8 smd paste+0 mask+0.05: 1(-1.475,0) 2(1.475,0)
  silkscreen extent -0.55,-0.9 0.55,0.9, body extent -1.6,-0.8 1.6,0.8, height 1.05
SMB-Bi [mil] "Molded Diode, 2-Leads, Body 5.4x3.6mm, IPC Medium Density, based on OnSemi component dimensions"
  rect 85x107.99 smd: 1(-87.01,0) 2(87.01,0)
  silkscreen extent -125,-79 125,79, body extent -104,-73 104,73, height 89
SOD-123 [mm] "On Semi recommended land pattern"
  rect 0.915x1.22 smd: 1(-1.637,0) 2(1.637,0)
  silkscreen extent -2.74,-1.17 2.03,1.08, body extent -1.93,-0.9 1.93,0.9, height 1.35
TCBT123 [mm]
  rrect30% 0.79x1.68 smd: 1(-1.27,-1.61) 2(1.27,-1.61) 4(-1.27,1.61)
  round 0.584 hole 0.33 mask+0.102: 3(0.135,1.11) 3(0.135,2.11) 3(0.635,1.61) 3(1.135,2.11) 3(1.135,1.11) 5(-1.27,0) 5(0,0) 5(0,-2.04) 5(0,-0.97) 5(1.27,0)
  rrect20% 2.06x1.68 smd: 3(0.635,1.61)
  round 0.025 smd mask+0.1: 5(0,-1.052)
  Top Layer region: 0.276,-2.45 0.322,-2.441 0.36,-2.415 0.386,-2.377 0.395,-2.331 0.395,-2.331 0.395,-0.345 1.562,-0.345 1.601,-0.337 1.635,-0.315 1.657,-0.281 1.665,-0.242 1.665,-0.242 1.665,0.242 1.657,0.281 1.635,0.315 1.601,0.337 1.562,0.345 1.562,0.345 -1.562,0.345 -1.601,0.337 -1.635,0.315 -1.657,0.281 -1.665,0.242 -1.665,0.242 -1.665,-0.242 -1.657,-0.281 -1.635,-0.315 -1.601,-0.337 -1.562,-0.345 -1.562,-0.345 -0.395,-0.345 -0.395,-2.331 -0.386,-2.377 -0.36,-2.415 -0.322,-2.441 -0.276,-2.45 -0.276,-2.45
  silkscreen extent -1.91,-2.9 1.91,1.9, body extent -1.91,-2.37 1.91,2.37, height 3.66
TDFN8 [mm]
  rrect30% 0.75x0.3 smd paste+0 mask+0.05: 1(-1.5,0.75) 2(-1.5,0.25) 3(-1.5,-0.25) 4(-1.5,-0.75) 5(1.478,-0.75) 6(1.478,-0.25) 7(1.478,0.25) 8(1.478,0.75)
  round 0.327 hole 0.2 mask+0.05: 9(-0.5,0) 9(0,0.5) 9(0,0) 9(0,-0.5) 9(0.5,0)
  rrect10% 1.36x1.46 smd paste+0 mask+0.05: 9(0,0)
  silkscreen extent -1.89,1.18 -1.79,1.33, body extent -1.5,-1 1.5,1, height 0.76
TI_Stacked_Overlay_Small [mil]
  silkscreen extent -418,-98 418,98
TSW-103-07-X-S [mm] "Samtec Header, 100mil, 1x3"
  rect 1.65x1.65 hole 1.016: 1(-2.54,0)
  round 1.65 hole 1.016: 2(0,0) 3(2.54,0)
  silkscreen extent -4.06,-2.19 4.06,1.52, body extent -3.81,-1.27 3.81,1.27, height 8.38
WEEE_Minimum [mil] "WEEElie bin"
  silkscreen extent -95,-172 99,104
Wurth_60900213421 [mil] "Shunt, 2.54mm, Black"
  round 1 on Mech3: 0(0,0)
  body extent -98,-48 98,48, height 236
XGL4020 [mm]
  rrect10% 0.98x3.4 smd paste+0 mask+0: 1(-1.185,0) 2(1.185,0)
  silkscreen extent -2.67,-2.15 2.15,2.15, body extent -2.25,-2.25 2.25,2.25, height 0.25
YFF0012AKAD [mm] "TI DSBGA 1.675x1.418mm"
  round 0.225 smd paste-0.13 mask+0: A1(-0.4,0.6) A2(0,0.6) A3(0.4,0.6) B1(-0.4,0.2) B2(0,0.2) B3(0.4,0.2) C1(-0.4,-0.2) C2(0,-0.2) C3(0.4,-0.2) D1(-0.4,-0.6) D2(0,-0.6) D3(0.4,-0.6)
  silkscreen extent -0.8,-0.92 0.8,0.92, body extent -0.71,-0.84 0.71,0.84, height 0.63
YZP0008ADAD [mm] "BGA, 8-Leads, Body 1.9x0.9mm, Pitch 0.5mm"
  round 0.23 smd paste-0.12 mask+0.05: A1(-0.25,0.75) A2(0.25,0.75) B1(-0.25,0.25) B2(0.25,0.25) C1(-0.25,-0.25) C2(0.25,-0.25) D1(-0.25,-0.75) D2(0.25,-0.75)
  silkscreen extent -0.6,-1.1 0.6,1.1, body extent -0.46,-0.96 0.46,0.96, height 0.51

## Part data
C1: library part CMP-0007730-2, "CAP, CERM, 1 uF, 50 V, +/- 10%, X7R, 0805", Cap_Case=0805, Manufacturer=Kemet, Supplier Part Number 1=399-7409-1-ND, TempCo=X7R, Tolerance_%=10%, Value1=Unknown, Value2=50V, ValueDisplayed=1uF
C2 C3: library part capcc02687, "CAP CER 1UF 50V X7R 0805", Manufacturer="TDK Corporation", Operating Temperature="-55°C ~ 125°C", Ratings=-, Supplier Part Number 1=445-7547-1-ND, Temperature Coefficient=X7R, Tolerance=±10%, Voltage - Rated=50V
C4 C37 C48 C67 C68 C69 C70 C71 C72 C77 C78 C79 C80 C81 C82 C95 C96 C113 C122 C159 C160 C161 C162 C163 C164 C165 C166 C167 C168 C169 C170 C171 C172 C262: library part CMP-0006607-2, "CAP, CERM, 0.1 uF, 25 V, +/- 10%, X5R, 0402", Cap_Case=0402, Manufacturer=MuRata, Supplier Part Number 1=490-5920-1-ND, TempCo=X5R, Tolerance_%=10%, Value1=Unknown, Value2=25V, ValueDisplayed=0.1uF
C5 C6: library part capcc03751, "CAP CER 1000PF 50V X7R 0603", Manufacturer="TDK Corporation", Operating Temperature="-55°C ~ 125°C", Ratings=AEC-Q200, Supplier Part Number 1=445-5659-1-ND, Temperature Coefficient=X7R, Tolerance=±10%, Voltage - Rated=50V
C7 C9 C15 C28 C29 C39 C174: library part capcc03515, "CAP CER 10UF 25V X5R 0805", Manufacturer="KYOCERA AVX", Operating Temperature="-55°C ~ 85°C", Ratings=-, Supplier Part Number 1=478-08053D106KAT4ACT-ND, Temperature Coefficient=X5R, Tolerance=±10%, Voltage - Rated=25V
C8 C10 C26: library part capcc03139, "CAP CER 4.7UF 10V X5R 0402", Manufacturer="TDK Corporation", Operating Temperature="-55°C ~ 85°C", Ratings=-, Supplier Part Number 1=445-175214-1-ND, Temperature Coefficient=X5R, Tolerance=±10%, Voltage - Rated=10V
C11 C12 C35 C36: library part capcc03627, "CAP CER 47UF 16V X5R 1210", Manufacturer="KYOCERA AVX", Operating Temperature="-55°C ~ 85°C", Ratings=-, Supplier Part Number 1=478-11989-1-ND, Temperature Coefficient=X5R, Tolerance=±10%, Voltage - Rated=16V
C13 C14 C27 C146: library part capcc05574, "CAP CER 10000PF 10V X7R 0402", Manufacturer="KYOCERA AVX", Operating Temperature="-55°C ~ 125°C", Ratings=-, Supplier Part Number 1=478-10790-1-ND, Temperature Coefficient=X7R, Tolerance=±20%, Voltage - Rated=10V
C16 C40 C175: library part capcc04225, "CAP CER 2200PF 25V X7R 0402", Manufacturer="KYOCERA AVX", Operating Temperature="-55°C ~ 125°C", Ratings=-, Supplier Part Number 1=478-12619-1-ND, Temperature Coefficient=X7R, Tolerance=±5%, Voltage - Rated=25V
C17 C18 C19 C20 C21 C22 C24 C25 C33 C34 C41 C42 C43 C44 C45 C46 C176 C177 C178 C179: library part capcc09395, "CAP CER 22UF 10V X7S 0805", Manufacturer="TDK Corporation", Operating Temperature="-55°C ~ 125°C", Ratings=-, Supplier Part Number 1=445-14560-1-ND, Temperature Coefficient=X7S, Tolerance=±20%, Voltage - Rated=10V
C23 C47 C180: library part capcc05896, "CAP CER 0.022UF 25V X7R 0402", Manufacturer="TDK Corporation", Operating Temperature="-55°C ~ 125°C", Ratings=AEC-Q200, Supplier Part Number 1=445-12246-1-ND, Temperature Coefficient=X7R, Tolerance=±20%, Voltage - Rated=25V
C30 C31: library part capcc01256, "CAP CER 0.1UF 25V X5R 0402", Manufacturer="KYOCERA AVX", Operating Temperature="-55°C ~ 85°C", Ratings=-, Supplier Part Number 1=478-7869-1-ND, Temperature Coefficient=X5R, Tolerance=±10%, Voltage - Rated=25V
C32 C64 C65 C66 C73 C74 C75 C76 C83 C84 C85 C86 C87 C88 C89 C90 C91 C92 C93 C130 C131 C134 C135 C136 C138 C139 C140 C141 C142 C143 C144 C148 C149 C150 C151 C152 C153 C155 C156 C157 C173 C190 C191 C192 C193 C194 C195 C196 C197 C198 C199 C200 C201 C202 C203 C204 C205 C206 C207 C208 C209 C210 C211 C212 C213 C214 C215 C216 C217 C218 C219 C220 C221 C222 C223 C224 C225 C226 C227 C228 C229 C230 C231 C232 C233 C234 C235 C236 C237 C238 C239 C240 C241 C242 C243 C244 C245 C246 C247 C248 C249 C250 C251 C256 C257 C258 C259 C260 C261 C265 C266 C273 C278 C279 C286: library part 0201RFCaps0693, "Broadband Capacitors", Alt Manufacturer="Murata Electronics", Alt PartNumber=GRM033C71C104ME14D, Manufacturer="Passive Plus", Operating Temperature="-55°C ~ 125°C", Temperature Coefficient="C0G, NP0", Tolerance=±10%, Voltage - Rated=16V
C38 C98 C106: library part capcc03112, "CAP CER 2.2UF 10V X5R 0402", Manufacturer="TDK Corporation", Operating Temperature="-55°C ~ 85°C", Ratings=-, Supplier Part Number 1=445-7392-1-ND, Temperature Coefficient=X5R, Tolerance=±10%, Voltage - Rated=10V
C49 C114 C123: library part capcc01277, "CAP CER 0.1UF 6.3V X5R 0402", Manufacturer="KYOCERA AVX", Operating Temperature="-55°C ~ 85°C", Ratings=-, Supplier Part Number 1=478-11504-1-ND, Temperature Coefficient=X5R, Tolerance=±10%, Voltage - Rated=6.3V
C50 C55 C59 C62 C63 C115 C120: library part dcp00009, "CAP FEEDTHRU 1UF 20% 6.3V 0603", Current="4 A", Manufacturer="Murata Electronics", Operating Temperature="-55°C ~ 105°C", Supplier Part Number 1=490-6970-1-ND, Temperature Coefficient=-, Tolerance=±20%, Voltage - Rated=6.3V
C51 C97 C100 C104 C105 C108 C112 C116 C124 C147: library part capcc03657, "CAP CER 10UF 10V X5R 0603", Manufacturer="KYOCERA AVX", Operating Temperature="-55°C ~ 85°C", Ratings=-, Supplier Part Number 1=478-10766-1-ND, Temperature Coefficient=X5R, Tolerance=±10%, Voltage - Rated=10V
C52 C56 C117 C121 C125 C128: library part capcc02750, "CAP CER 1UF 25V X5R 0402", Manufacturer="TDK Corporation", Operating Temperature="-55°C ~ 85°C", Ratings=-, Supplier Part Number 1=445-9066-1-ND, Temperature Coefficient=X5R, Tolerance=±10%, Voltage - Rated=25V
C53 C57 C60 C101 C109 C118 C126: library part capcc09400, "CAP CER 10UF 25V X5R 0603", Manufacturer=Murata, Operating Temperature="-55°C ~ 85°C", Ratings=-, Supplier Part Number 1=490-GRM188R61E106KA73JCT-ND, Temperature Coefficient=X5R, Tolerance=±10%, Voltage - Rated=25V
C54 C58 C61 C102 C110 C119 C127: library part capcc09401, "CAP CER 0.1UF 25V X7R 0402", Manufacturer=Murata, Operating Temperature="-55°C ~ 125°C", Ratings=-, Temperature Coefficient=X7R, Tolerance=±10%, Voltage - Rated=25V
C94: library part capcc03566, "CAP CER 10UF 10V X5R 0603", Manufacturer="TDK Corporation", Operating Temperature="-55°C ~ 85°C", Ratings=-, Supplier Part Number 1=445-C1608X5R1A106K080ACCT-ND, Temperature Coefficient=X5R, Tolerance=±10%, Voltage - Rated=10V
C99 C103 C107 C111: library part capcc09264, "CAP CER 1UF 10V X5R 0201", Manufacturer="Murata Electronics", Operating Temperature="-55°C ~ 85°C", Ratings=-, Supplier Part Number 1=490-GRM033R61A105ME44DCT-ND, Temperature Coefficient=X5R, Tolerance=±20%, Voltage - Rated=10V
C129 C132 C133 C137 C145 C252 C253 C254 C255: library part dcp00005, "CAP FEEDTHRU 0.47UF 6.3V 0402", Current="2 A", Manufacturer=Murata, Operating Temperature="-55°C ~ 85°C", Supplier Part Number 1=490-16920-1-ND, Temperature Coefficient=-, Tolerance=±20%, Voltage - Rated=6.3V
C154 C158: library part capcc06404, "CAP CER SMD", Manufacturer="KYOCERA AVX", Operating Temperature="-55°C ~ 125°C", Ratings=-, Supplier Part Number 1=478-02015C101KAT2ACT-ND, Temperature Coefficient=X7R, Tolerance=±10%, Voltage - Rated=50V
C181 C184 C186 C264: library part CMP-0007108-5, "CAP, CERM, 22 uF, 10 V, +/- 20%, X5R, 0603", Cap_Case=0603, Manufacturer="Samsung Electro-Mechanics", TempCo=X5R, Tolerance_%=20%, Value1=Unknown, Value2=10V, ValueDisplayed=22uF
C182 C185 C187 C189 C274 C275: library part CMP-0006302-2, "CAP, CERM, 2.2 uF, 10 V, +/- 10%, X7S, 0402", Cap_Case=0402_065, Manufacturer=TDK, Supplier Part Number 1=445-9097-1-ND, TempCo=X7S, Tolerance_%=10%, Value1="0.005925 ohm", Value2=10V, ValueDisplayed=2.2uF
C183 C188: library part CMP-0078218-1, "CAP, CERM, 0.01 µF, 16 V,+/- 10%, X7R, 0402", Cap_Case=0402, Manufacturer=Kemet, Supplier Part Number 1=399-1038-1-ND, TempCo=X7R, Tolerance_%=10%, Value2=16V, ValueDisplayed=0.01µF
C263 C276: library part CMP-0009781-1, "CAP, CERM, 0.22 uF, 10 V, +/- 20%, X5R, 0201", Cap_Case=0201, Manufacturer="Taiyo Yuden", Supplier Part Number 1=587-2483-1-ND, TempCo=X5R, Tolerance_%=20%, Value1=Unknown, Value2=10V, ValueDisplayed=0.22uF
C267 C268 C270 C271 C280 C282: library part CMP-2010-01978-1, "02013J0R5PBSTR\500", Manufacturer="AVX Interconnect / Elco"
C269 C272 C281 C283: library part CMP-2010-02058-1, "02015J0R8PBSTR", Manufacturer="AVX Interconnect / Elco"
D1: library part CMP-0028547-2, "Diode, Schottky, 30 V, 1 A, SOD-123", Manufacturer="ON Semiconductor", Value1=1A, Value2=0.47V
D2: library part CMP-0006044-3, "Diode, TVS, Bi, 15 V, 24.4 Vc, SMB", Manufacturer="Fairchild Semiconductor", Value1=600W
D3: library part cmp00247, "LED GREEN CLEAR CHIP SMD", Alt Manufacturer=-, Color=Green, Current Rating (Amps)=20mA, Manufacturer="Lite-On Inc.", Supplier Part Number 1=160-1888-1-ND, Voltage - Forward (Vf) (Typ)=3.2V
F1: library part cmp00082, "FUSE BOARD MOUNT 2.5A 32VDC 1206", Alt Manufacturer=-, Current Rating (Amps)="2.5 A", Manufacturer="Bourns Inc.", Supplier Part Number 1=SF-1206FP250-2CT-ND, Voltage Rating - DC="32 V"
FB1 FB2 FB6 FB7 FB8 FB9 FB10: library part dcp00004, "8.5 Ohms @ 100 MHz 1 Power Line Ferrite Bead 0603 (1608 Metric) 8A 4mOhm", Current=8A, Manufacturer=Murata, Operating Temperature="-55°C ~ 125°C", Supplier Part Number 1=490-BLE18PS080SN1DCT-ND, Temperature Coefficient=-
FB3 FB4 FB5: library part dcp00247, "FERRITE BEAD 30 OHM 0603 1LN", Current=1A, Manufacturer="Murata Electronics", Operating Temperature="-55°C ~ 125°C", Supplier Part Number 1=490-1035-1-ND, Temperature Coefficient=-
FC1 FC2 FC3 FC4 FC5 FC6 FC7 FC8 FC9 FC10 FC11 FC12 FC13 FC14: library part dcp00001, "Feed through capactior 27uF", Current=6A, Manufacturer=Murata, Operating Temperature="-40°C ~ 85°C", PartNumber=NFM31PC276B0J3L, Supplier Part Number 1=490-6984-1-ND, Temperature Coefficient=-, Tolerance=±20%, Voltage - Rated=6.3V
FID1 FID2 FID3 fid4 fid5 fid6: library part cmp00099, "Fiducial", Alt Manufacturer=-
H3 H4: library part cmp00097, "Hex Standoff Threaded #4-40 Stainless Steel 1.250\" (31.75mm) 1 1/4", Alt Manufacturer=-, Manufacturer="RAF Electronic Hardware", Supplier Part Number 1=1772-1827-ND
J1: library part cmp00011, "Connector, 1.27mm, 40x10, Black, SMT", Alt Manufacturer=-, Manufacturer=Samtec, Supplier Part Number 1=SAM9173-ND
J2: library part cmp00022, "Power Jack, mini, 2.1mm OD, R/A, TH", Alt Manufacturer=-, Manufacturer=Switchcraft, Supplier Part Number 1=SC1313-ND
J3: library part cmp00020, "Header, 2.54mm, 2x1, Vertical, TH", Alt Manufacturer=Molex, Alt PartNumber=0022232021, Color=-, Supplier Part Number 1=900-0022232021-ND
J4 J5 J7 J8 J10 J11: library part cmp00028, "SMA Connector Jack, Female Socket 50Ohm Surface Mount, Through Hole Solder", Alt Manufacturer=-, Manufacturer="Amphenol RF", Supplier Part Number 1=ACX1962-ND
J6: library part cmp00061, "FTDI Dongle EVM Mating connector and standoff holes", Alt Manufacturer=-, Manufacturer=Samtec, Supplier Part Number 1=SAM8180-ND
J9: library part cmp00032, "SMP Connector Plug, Male Pin 50Ohm Surface Mount Solder", Alt Manufacturer=-, Manufacturer=Molex, Supplier Part Number 1=WM3891CT-ND, Voltage_V=335V
J12 J14 J16 J18: library part cmp00014, "Header, 100mil, 2x1, Gold, TH", Alt Manufacturer=-, Manufacturer="Sullins Connector Solutions", Supplier Part Number 1=S1011E-02-ND
J13 J17: library part CMP-0075407-1, "Header, 100mil, 3x1, Gold, TH", Color=Black, Current_A=6.3A, Manufacturer=Samtec, Supplier Part Number 1=SAM1029-03-ND, Voltage_V=550V
J15 J19: library part CMP-0084540-2, "50 Ohm JACK, SMT", Manufacturer="Cinch Connectivity"
L1: library part LSMT56800072, "FIXED IND 1.5UH 11.1A 14.3 MOHM", Current - Saturation (Isat)=7.5A, Current Rating (Amps)="11.1 A", DC Resistance (DCR)="14.3mOhm Max", Frequency - Self Resonant=45MHz, Inductance="1.5 µH", Inductance Frequency - Test="1 MHz", Manufacturer=COILCRAFT, Operating Temperature="-40°C ~ 125°C", Q @ Freq=-, Ratings=AEC-Q200, Supplier Part Number 1=2457-XGL4020-152MEC-ND, Tolerance=±20%
L3: library part CMP-06042-005882-1, "Film type RF Inductor 2nH ±0.05nH 600mA 0.12Ω 0201 (0603). LQP03HQ2N0W02D", Manufacturer="Murata Electronics", Part Number=LQP03HQ2N0W02D
L4 L5 L6 L7 L8 L9 L10: library part CMP-06042-005882-1, "Film type RF Inductor 2nH ±0.05nH 600mA 0.12Ω 0201 (0603). LQP03HQ2N0W02D", Part Number=LQP03HQ2N0W02D
LBL1: library part cmp00106, "Thermal Transfer Printable Labels, 0.650\" W x 0.200\" H - 10,000 per roll", Alt Manufacturer=-, Manufacturer=Brady, Supplier Part Number 1=2267-THT-14-423-10-ND
Logo1: library part cmp00105, "FDL", Alt Manufacturer=-
LOGO2: library part cmp00100, "IEC 61010-1 Hot Surface Warning", Alt Manufacturer=-, PartNumber=IEC_HotSurface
